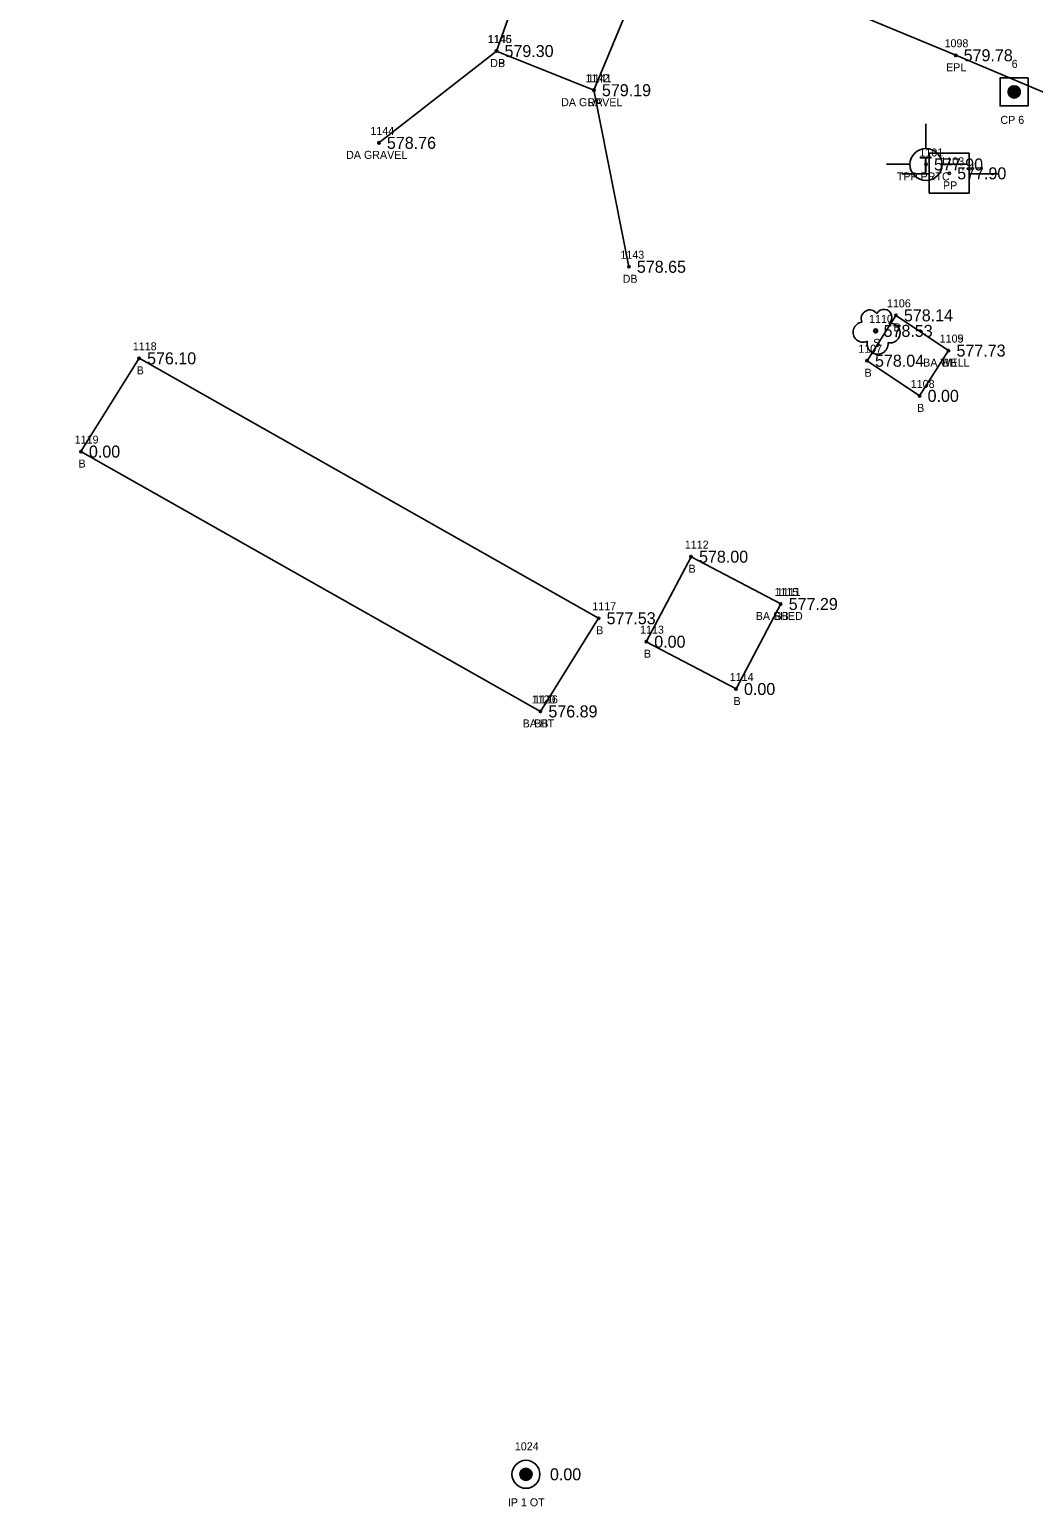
# Model space of a CAD drawing. Extents: x 1664393 to 1667175, y 987029 to 988607.
# Drawn here: x 1665028.1 to 1665153.6, y 987728.7 to 987913.2 of the extents above; entities that cross this region are included whole.
import ezdxf

# ---------------------------------------------------------------- set-up
doc = ezdxf.new("R2010")
doc.units = 0
for name, color, linetype in [('RD_EX_Bldg', 7, 'Continuous'), ('RD_EX_Bldg_txCode', 7, 'Continuous'), ('RD_EX_Driveway', 7, 'Continuous'), ('RD_EX_Driveway_txCode', 7, 'Continuous'), ('RD_EX_DV_Prop_txCode', 7, 'Continuous'), ('RD_EX_DV_PropPin', 7, 'Continuous'), ('RD_EX_Road', 7, 'Continuous'), ('RD_EX_Road_txCode', 7, 'Continuous'), ('RD_EX_TX_Bldg_ELEV', 7, 'Continuous'), ('RD_EX_TX_Driveway_ELEV', 7, 'Continuous'), ('RD_EX_TX_DV_Prop_ELEV', 7, 'Continuous'), ('RD_EX_TX_Road_ELEV', 7, 'Continuous'), ('RD_EX_TX_UT_ELEV', 7, 'Continuous'), ('RD_EX_TX_VEG_ELEV', 7, 'Continuous'), ('RD_EX_UT', 7, 'Continuous'), ('RD_EX_UT_txCode', 7, 'Continuous'), ('RD_EX_VEG', 7, 'Continuous'), ('RD_EX_VEG_txCode', 7, 'Continuous'), ('RD_HC_Survey', 7, 'Continuous'), ('RD_HC_Survey_ELEV', 7, 'Continuous'), ('RD_HC_Survey_txCode', 7, 'Continuous'), ('RD_SMD_Locator', 7, 'Continuous')]:
    doc.layers.add(name, color=color, linetype=linetype)

msp = doc.modelspace()

# ---------------------------------------------------------------- linework, layer by layer
at = {"layer": 'RD_EX_Bldg'}
for points in [[(1665143.02, 987873.08), (1665136.45, 987877.48), (1665132.84, 987871.81), (1665139.41, 987867.42), (1665143.02, 987873.08)], [(1665092.01, 987828), (1665099.28, 987839.64), (1665041.84, 987872.11), (1665034.57, 987860.46), (1665092.01, 987828)], [(1665122.05, 987841.42), (1665110.84, 987847.33), (1665105.24, 987836.71), (1665116.46, 987830.8), (1665122.05, 987841.42)]]:
    msp.add_lwpolyline(points, dxfattribs=at)
at = {"layer": 'RD_EX_Driveway'}
for p, q in [((1665071.82, 987899.03), (1665086.52, 987910.5)), ((1665098.7, 987905.61), (1665103.07, 987883.55))]:
    msp.add_line(p, q, dxfattribs=at)
msp.add_lwpolyline([(1665117.43, 987920.99), (1665108.9, 987920.09), (1665103.43, 987917.07), (1665098.7, 987905.61), (1665086.52, 987910.5), (1665090.17, 987920.87), (1665090.28, 987927.13), (1665086.22, 987934.27)], dxfattribs=at)
at = {"layer": 'RD_EX_DV_PropPin'}
for p, q in [((1665089.46, 987732.49), (1665089.46, 987732.88)), ((1665089.5, 987732.39), (1665089.5, 987732.99)), ((1665089.53, 987732.32), (1665089.53, 987733.06)), ((1665089.57, 987732.26), (1665089.57, 987733.12)), ((1665089.6, 987732.21), (1665089.6, 987733.16)), ((1665089.64, 987732.17), (1665089.64, 987733.2)), ((1665089.67, 987732.14), (1665089.67, 987733.24)), ((1665089.71, 987732.11), (1665089.71, 987733.27)), ((1665089.74, 987732.08), (1665089.74, 987733.3)), ((1665089.78, 987732.05), (1665089.78, 987733.32)), ((1665089.81, 987732.03), (1665089.81, 987733.35)), ((1665089.85, 987732.01), (1665089.85, 987733.36)), ((1665089.88, 987732), (1665089.88, 987733.38)), ((1665089.92, 987731.98), (1665089.92, 987733.4)), ((1665089.95, 987731.97), (1665089.95, 987733.41)), ((1665089.99, 987731.96), (1665089.99, 987733.42)), ((1665090.02, 987731.95), (1665090.02, 987733.43)), ((1665090.06, 987731.94), (1665090.06, 987733.44)), ((1665090.09, 987731.94), (1665090.09, 987733.44)), ((1665090.13, 987731.93), (1665090.13, 987733.45)), ((1665090.16, 987731.93), (1665090.16, 987733.45)), ((1665090.2, 987731.93), (1665090.2, 987733.45)), ((1665090.23, 987731.93), (1665090.23, 987733.45)), ((1665090.27, 987731.93), (1665090.27, 987733.45)), ((1665090.3, 987731.94), (1665090.3, 987733.44)), ((1665090.34, 987731.94), (1665090.34, 987733.44)), ((1665090.37, 987731.95), (1665090.37, 987733.43)), ((1665090.41, 987731.96), (1665090.41, 987733.42)), ((1665090.44, 987731.97), (1665090.44, 987733.41)), ((1665090.48, 987731.98), (1665090.48, 987733.4)), ((1665090.51, 987732), (1665090.51, 987733.38)), ((1665090.55, 987732.01), (1665090.55, 987733.36)), ((1665090.58, 987732.03), (1665090.58, 987733.35)), ((1665090.62, 987732.05), (1665090.62, 987733.32)), ((1665090.65, 987732.08), (1665090.65, 987733.3)), ((1665090.69, 987732.11), (1665090.69, 987733.27)), ((1665090.72, 987732.14), (1665090.72, 987733.24)), ((1665090.76, 987732.17), (1665090.76, 987733.2)), ((1665090.79, 987732.21), (1665090.79, 987733.16)), ((1665090.83, 987732.26), (1665090.83, 987733.12)), ((1665090.86, 987732.32), (1665090.86, 987733.06)), ((1665090.9, 987732.39), (1665090.9, 987732.99)), ((1665090.93, 987732.49), (1665090.93, 987732.88))]:
    msp.add_line(p, q, dxfattribs=at)
for radius in [1.75, 0.761]:
    msp.add_circle((1665090.2, 987732.69), radius, dxfattribs=at)
at = {"layer": 'RD_EX_Road'}
msp.add_lwpolyline([(1665498.75, 987759.37), (1665465.87, 987774.2), (1665419.78, 987793.88), (1665373.62, 987813.14), (1665327.95, 987832.31), (1665281.42, 987852.3), (1665236.13, 987871.34), (1665189.6, 987890.71), (1665143.92, 987909.97), (1665117.43, 987920.99), (1665086.22, 987934.27), (1665051.62, 987948.55), (1665005.38, 987968.44), (1664960.17, 987987.67), (1664913.53, 988007.62), (1664868.21, 988026.81)], dxfattribs=at)
at = {"layer": 'RD_EX_UT'}
for p, q in [((1665140.21, 987901.4), (1665140.21, 987898.33)), ((1665145.6, 987897.73), (1665140.6, 987897.73)), ((1665140.6, 987897.73), (1665140.6, 987892.73)), ((1665145.6, 987892.73), (1665145.6, 987897.73)), ((1665135.28, 987896.35), (1665138.21, 987896.35)), ((1665137.17, 987895.17), (1665140.64, 987895.17)), ((1665142.21, 987896.35), (1665145.28, 987896.35)), ((1665145.53, 987895.17), (1665149.17, 987895.17)), ((1665140.6, 987892.73), (1665145.6, 987892.73))]:
    msp.add_line(p, q, dxfattribs=at)
msp.add_circle((1665140.21, 987896.33), 2, dxfattribs=at)
at = {"layer": 'RD_EX_VEG'}
msp.add_circle((1665133.91, 987875.54), 0.25, dxfattribs=at)
for centre, radius, start, end in [((1665133.19, 987877.08), 1.08, 34.9763, 204.756), ((1665134.96, 987877.24), 0.995, 308.7626, 152.0467), ((1665132.35, 987875.38), 1.26, 96.4518, 294.734), ((1665135.75, 987875.26), 1.22, 256.5667, 98.1046), ((1665134.16, 987873.94), 1.32, 166.8827, 5.7589)]:
    msp.add_arc(centre, radius, start, end, dxfattribs=at)
at = {"layer": 'RD_HC_Survey'}
for p, q in [((1665150.51, 987905.14), (1665150.51, 987905.67)), ((1665150.53, 987905.08), (1665150.53, 987905.73)), ((1665150.56, 987905.03), (1665150.56, 987905.78)), ((1665150.58, 987904.99), (1665150.58, 987905.82)), ((1665150.61, 987904.95), (1665150.61, 987905.85)), ((1665150.63, 987904.92), (1665150.63, 987905.89)), ((1665150.66, 987904.89), (1665150.66, 987905.92)), ((1665150.68, 987904.87), (1665150.68, 987905.94)), ((1665150.71, 987904.84), (1665150.71, 987905.97)), ((1665150.73, 987904.82), (1665150.73, 987905.99)), ((1665150.75, 987904.8), (1665150.75, 987906.01)), ((1665150.78, 987904.78), (1665150.78, 987906.03)), ((1665150.8, 987904.76), (1665150.8, 987906.04)), ((1665150.83, 987904.75), (1665150.83, 987906.06)), ((1665150.85, 987904.73), (1665150.85, 987906.07)), ((1665150.88, 987904.72), (1665150.88, 987906.09)), ((1665150.9, 987904.71), (1665150.9, 987906.1)), ((1665150.93, 987904.7), (1665150.93, 987906.11)), ((1665150.95, 987904.69), (1665150.95, 987906.12)), ((1665150.98, 987904.68), (1665150.98, 987906.13)), ((1665151, 987904.67), (1665151, 987906.14)), ((1665151.03, 987904.66), (1665151.03, 987906.15)), ((1665151.05, 987904.66), (1665151.05, 987906.15)), ((1665151.08, 987904.65), (1665151.08, 987906.16)), ((1665151.1, 987904.65), (1665151.1, 987906.16)), ((1665151.13, 987904.64), (1665151.13, 987906.17)), ((1665151.15, 987904.64), (1665151.15, 987906.17)), ((1665151.18, 987904.64), (1665151.18, 987906.17)), ((1665151.2, 987904.64), (1665151.2, 987906.17)), ((1665151.23, 987904.63), (1665151.23, 987906.17)), ((1665151.25, 987904.63), (1665151.25, 987906.17)), ((1665151.27, 987904.64), (1665151.27, 987906.17)), ((1665151.3, 987904.64), (1665151.3, 987906.17)), ((1665151.32, 987904.64), (1665151.32, 987906.17)), ((1665151.35, 987904.64), (1665151.35, 987906.16)), ((1665151.37, 987904.65), (1665151.37, 987906.16)), ((1665151.4, 987904.65), (1665151.4, 987906.16)), ((1665151.42, 987904.66), (1665151.42, 987906.15)), ((1665151.45, 987904.67), (1665151.45, 987906.14)), ((1665151.47, 987904.67), (1665151.47, 987906.13)), ((1665151.5, 987904.68), (1665151.5, 987906.13)), ((1665151.52, 987904.69), (1665151.52, 987906.12)), ((1665151.55, 987904.7), (1665151.55, 987906.11)), ((1665151.57, 987904.71), (1665151.57, 987906.09)), ((1665151.6, 987904.73), (1665151.6, 987906.08)), ((1665151.62, 987904.74), (1665151.62, 987906.07)), ((1665151.65, 987904.76), (1665151.65, 987906.05)), ((1665151.67, 987904.77), (1665151.67, 987906.04)), ((1665151.7, 987904.79), (1665151.7, 987906.02)), ((1665151.72, 987904.81), (1665151.72, 987906)), ((1665151.74, 987904.83), (1665151.74, 987905.98)), ((1665151.77, 987904.85), (1665151.77, 987905.95)), ((1665151.79, 987904.88), (1665151.79, 987905.93)), ((1665151.82, 987904.91), (1665151.82, 987905.9)), ((1665151.84, 987904.94), (1665151.84, 987905.87)), ((1665151.87, 987904.97), (1665151.87, 987905.84)), ((1665151.89, 987905.01), (1665151.89, 987905.8)), ((1665151.92, 987905.06), (1665151.92, 987905.75)), ((1665151.94, 987905.11), (1665151.94, 987905.7)), ((1665151.97, 987905.18), (1665151.97, 987905.63)), ((1665150.48, 987905.23), (1665150.48, 987905.58)), ((1665151.99, 987905.29), (1665151.99, 987905.52))]:
    msp.add_line(p, q, dxfattribs=at)
msp.add_lwpolyline([(1665152.98, 987907.15), (1665149.48, 987907.15), (1665149.48, 987903.65), (1665152.98, 987903.65)], close=True, dxfattribs=at)
msp.add_circle((1665151.23, 987905.4), 0.769, dxfattribs=at)
at = {"layer": 'RD_SMD_Locator'}
for centre in [(1665086.52, 987910.5), (1665086.52, 987910.5), (1665143.92, 987909.97), (1665098.7, 987905.61), (1665098.7, 987905.61), (1665151.23, 987905.4), (1665071.82, 987899.03), (1665140.21, 987896.33), (1665143.11, 987895.22), (1665103.07, 987883.55), (1665136.45, 987877.48), (1665133.91, 987875.54), (1665143.02, 987873.08), (1665143.02, 987873.08), (1665041.84, 987872.11), (1665132.84, 987871.81), (1665139.41, 987867.42), (1665034.57, 987860.46), (1665110.84, 987847.33), (1665122.05, 987841.42), (1665122.05, 987841.42), (1665099.28, 987839.64), (1665105.24, 987836.71), (1665116.46, 987830.8), (1665092.01, 987828), (1665092.01, 987828), (1665090.2, 987732.69)]:
    msp.add_circle(centre, 0.15, dxfattribs=at)

# ---------------------------------------------------------------- texts
at = {"layer": 'RD_EX_Bldg_txCode'}
for s, p in [('1106', (1665135.33, 987878.48)), ('B', (1665136.15, 987875.48)), ('1105', (1665141.92, 987874.08)), ('1109', (1665141.92, 987874.08)), ('1118', (1665041.06, 987873.11)), ('1107', (1665131.74, 987872.81)), ('B', (1665041.54, 987870.11)), ('B', (1665132.53, 987869.81)), ('BA WELL', (1665139.86, 987871.08)), ('BB', (1665142.24, 987871.08)), ('1108', (1665138.31, 987868.42)), ('B', (1665139.1, 987865.42)), ('1119', (1665033.79, 987861.46)), ('B', (1665034.27, 987858.46)), ('1112', (1665110.06, 987848.33)), ('B', (1665110.53, 987845.33)), ('1115', (1665121.27, 987842.42)), ('1111', (1665121.56, 987842.42)), ('1117', (1665098.5, 987840.64)), ('BA SHED', (1665118.93, 987839.42)), ('BB', (1665121.27, 987839.42)), ('B', (1665098.98, 987837.64)), ('1113', (1665104.47, 987837.71)), ('B', (1665104.94, 987834.71)), ('1114', (1665115.68, 987831.8)), ('1120', (1665090.91, 987829)), ('1116', (1665091.21, 987829)), ('B', (1665116.15, 987828.8)), ('BA HT', (1665089.79, 987826)), ('BB', (1665091.23, 987826))]:
    msp.add_text(s, height=1, dxfattribs=at).set_placement(p)
at = {"layer": 'RD_EX_Driveway_txCode'}
for s, p in [('1146', (1665085.43, 987911.5)), ('1145', (1665085.46, 987911.5)), ('DB', (1665085.74, 987908.5)), ('DP', (1665085.74, 987908.5)), ('1142', (1665097.64, 987906.61)), ('1141', (1665097.92, 987906.61)), ('DA GRAVEL', (1665094.6, 987903.61)), ('DP', (1665097.92, 987903.61)), ('1144', (1665070.76, 987900.03)), ('DA GRAVEL', (1665067.72, 987897.03)), ('1143', (1665102.01, 987884.55)), ('DB', (1665102.29, 987881.55))]:
    msp.add_text(s, height=1, dxfattribs=at).set_placement(p)
at = {"layer": 'RD_EX_DV_Prop_txCode'}
for s, p in [('1024', (1665088.81, 987735.69)), ('IP 1 OT', (1665087.94, 987728.69))]:
    msp.add_text(s, height=1, dxfattribs=at).set_placement(p)
at = {"layer": 'RD_EX_Road_txCode'}
for s, p in [('1098', (1665142.53, 987910.97)), ('EPL', (1665142.72, 987907.97))]:
    msp.add_text(s, height=1, dxfattribs=at).set_placement(p)
at = {"layer": 'RD_EX_TX_Bldg_ELEV'}
for s, p in [('578.14', (1665137.45, 987876.73)), ('576.10', (1665042.84, 987871.36)), ('578.04', (1665133.84, 987871.06)), ('577.73', (1665144.02, 987872.33)), ('577.73', (1665144.02, 987872.33)), ('0.00', (1665140.41, 987866.67)), ('0.00', (1665035.57, 987859.71)), ('578.00', (1665111.84, 987846.58)), ('577.29', (1665123.05, 987840.67)), ('577.29', (1665123.05, 987840.67)), ('577.53', (1665100.28, 987838.89)), ('0.00', (1665106.24, 987835.96)), ('0.00', (1665117.46, 987830.05)), ('576.89', (1665093.01, 987827.25)), ('576.89', (1665093.01, 987827.25))]:
    msp.add_text(s, height=1.5, dxfattribs=at).set_placement(p)
at = {"layer": 'RD_EX_TX_Driveway_ELEV'}
for s, p in [('579.30', (1665087.52, 987909.75)), ('579.30', (1665087.52, 987909.75)), ('579.19', (1665099.7, 987904.86)), ('579.19', (1665099.7, 987904.86)), ('578.76', (1665072.82, 987898.28)), ('578.65', (1665104.07, 987882.8))]:
    msp.add_text(s, height=1.5, dxfattribs=at).set_placement(p)
at = {"layer": 'RD_EX_TX_DV_Prop_ELEV'}
msp.add_text('0.00', height=1.5, dxfattribs=at).set_placement((1665093.2, 987731.94))
at = {"layer": 'RD_EX_TX_Road_ELEV'}
msp.add_text('579.78', height=1.5, dxfattribs=at).set_placement((1665144.92, 987909.22))
at = {"layer": 'RD_EX_TX_UT_ELEV'}
msp.add_text('577.90', height=1.5, dxfattribs=at).set_placement((1665141.21, 987895.58))
at = {"layer": 'RD_EX_TX_VEG_ELEV'}
msp.add_text('578.53', height=1.5, dxfattribs=at).set_placement((1665134.91, 987874.79))
at = {"layer": 'RD_EX_UT'}
msp.add_text('T', height=2, dxfattribs=at).set_placement((1665139.36, 987895.29))
at = {"layer": 'RD_EX_UT_txCode'}
for s, p in [('1101', (1665139.39, 987897.33)), ('1103', (1665142.01, 987896.22)), ('TPP PRTC', (1665136.56, 987894.33)), ('PP', (1665142.33, 987893.22))]:
    msp.add_text(s, height=1, dxfattribs=at).set_placement(p)
at = {"layer": 'RD_EX_VEG_txCode'}
for s, p in [('1110', (1665133.1, 987876.54)), ('S', (1665133.61, 987873.54))]:
    msp.add_text(s, height=1, dxfattribs=at).set_placement(p)
at = {"layer": 'RD_HC_Survey_ELEV'}
msp.add_text('577.90', height=1.5, dxfattribs=at).set_placement((1665144.11, 987894.47))
at = {"layer": 'RD_HC_Survey_txCode'}
for s, p in [('6', (1665150.92, 987908.4)), ('CP 6', (1665149.51, 987901.4))]:
    msp.add_text(s, height=1, dxfattribs=at).set_placement(p)

doc.saveas('drawing.dxf')
